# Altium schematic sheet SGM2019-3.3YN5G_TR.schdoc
size 127 x 101 mm
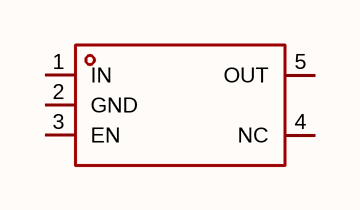
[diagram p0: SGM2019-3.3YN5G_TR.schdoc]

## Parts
U?  jsm2019-3.3yn5g/tr  [SOT-23-5_L2.9-W1.6-P0.95-LS2.8-BR]  (value not drawn)

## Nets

Not connected (* = marked no-connect by the designer): U? 1(IN) 2(GND) 3(EN) 4(NC) 5(OUT)

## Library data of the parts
U? = jsm2019-3.3yn5g/tr: 输出极性:正极;工作电压:5.5V;输出电压:3.3V;输出电流:300mA;电源纹波抑制比(PSRR):80dB@(100Hz);输出类型:固定;; Manufacturer: JSMSEMI(杰盛微); Symbol: SGM2019-3.3YN5G/TR; AddInBom: yes; ModelId: 7ba65df16e7b4570af156e925f9c37fe; ModelTransform: 114.173,114.173,0,90,0,0,0,0,0; Output Configuration: 正极; Voltage - Supply: 5.5V; Output Voltage: 3.3V; Output Current: 300mA; Voltage Dropout: 160mV@(300mA); standby current: 2uA; Output Type: 固定; Number of Outputs: 1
